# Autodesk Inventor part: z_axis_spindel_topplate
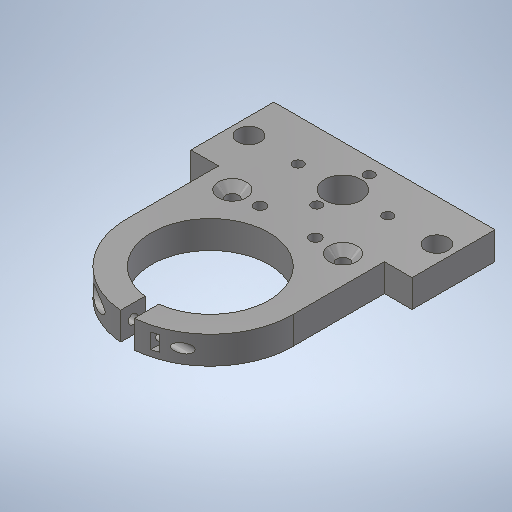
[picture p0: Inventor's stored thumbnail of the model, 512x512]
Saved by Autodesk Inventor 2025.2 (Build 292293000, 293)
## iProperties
Created: 2025-04
Part Number: z_axis_spindel_topplate
Material: 1.0037 S235JR
Document SubType Name: Modeling
Designer: BennF
Density: 7.85 g/cm^3
Appearance: Stahl
Author: BennF
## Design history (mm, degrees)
sketch "Sketch2"
  geometry: L1 (-2.5, -29.896)-(-2.5, -21.052); L2 (2.5, -29.896)-(2.5, -21.052); L3 (-30, 0)-(-30, 33); L4 (-40, 63)-(40, 63); L5 (30, 33)-(30, 0); L6 (-30, 33)-(-40, 33); L7 (-40, 33)-(-40, 63); L8 (30, 33)-(40, 33); L9 (40, 33)-(40, 63); A1 r 21.2 centre (0, 0) between (2.5, -21.052) and (-2.5, -21.052); A2 r 30 centre (0, 0) between (-30, 0) and (-2.5, -29.896); A3 r 30 centre (0, 0) between (2.5, -29.896) and (30, 0); 3 further points
  constraints: 18 end point, 7 point on circle, 4 perpendicular, 3 centre point, 3 coincident, 3 horizontal alignment, 3 vertical, 2 equal length, 2 horizontal, 1 midpoint, 1 tangent, 1 vertical alignment
  dimensions: "d0" = 5 distance between parallel lines of L2 L1; "d1" = 21.2 radius of A1; "d32" = 80 distance of L4.start L4.end; "d57" = 60 distance between parallel lines of L5 L3; "d58" = 30 distance of L4.end L8.end; "d86" = 63 distance from line of point (0, 0) L4
extrude "Extrusion1" new body sketch "Sketch2" distance "d4" = 10; taper "d5" = 0 deg
sketch "Sketch3"
  geometry: L1 (-10, 29.896)-(-10, 0) reference; L2 (-10, 0)-(0, 8.844); L3 (0, 29.896)-(0, 0) reference; L4 (0, 0)-(-10, 8.844); L5 (-10, 8.844)-(0, 8.844) reference; L6 (0, 8.844)-(0, 0) reference; L7 (0, 0)-(-10, 0) reference; L8 (-10, 0)-(-10, 8.844) reference; L9 (-10, 92.896)-(0, 92.896) reference; L10 (0, 92.896)-(0, 50.948) reference; L11 (0, 50.948)-(-10, 50.948) reference; L12 (-10, 50.948)-(-10, 92.896) reference; 2 further points
  constraints: 4 end point, 1 coincident, 1 midpoint
hole "Hole1" sketch "Sketch3" at (-5, 4.422) diameter "d6" = 3.4; stored, may be unused: countersink angle "d10" = 90 deg, drill point angle "d12" = 0 deg; dims "d7" = 3, "d8" = 6.5, "d9" = 3.4, "d11" = 3
sketch "Sketch4"
  geometry: L1 (10, 0)-(0, 0) reference; L2 (0, 0)-(0, 8.844) reference; L3 (0, 8.844)-(10, 8.844) reference; L4 (10, 8.844)-(10, 0) reference; L5 (0, 92.896)-(10, 92.896) reference; L6 (10, 92.896)-(10, 50.948) reference; L7 (10, 50.948)-(0, 50.948) reference; L8 (0, 50.948)-(0, 92.896) reference; L9 (0, 8.844)-(10, 0); L10 (0, 0)-(0, 29.896) reference; L11 (10, 8.844)-(0, 0); 2 further points
  constraints: 4 end point, 1 coincident, 1 midpoint
hole "Hole2" sketch "Sketch4" at (5, 4.422) diameter "d13" = 3.4 (= d6); stored, may be unused: countersink angle "d17" = 90 deg, drill point angle "d19" = 0 deg; dims "d14" = 6, "d15" = 4, "d16" = 2, "d18" = 8
workplane "Work Plane1"
sketch "Sketch5"
  geometry: L1 (5, 7.597)-(7.75, 6.01); L2 (7.75, 6.01)-(7.75, 2.834); L3 (7.75, 2.834)-(5, 1.246); L4 (5, 1.246)-(2.25, 2.834); L5 (2.25, 2.834)-(2.25, 6.01); L6 (2.25, 6.01)-(5, 7.597); L7 (7.75, 2.834)-(7.75, 0.848); L8 (10, 49.725)-(0, 49.725) reference; L9 (10, 10.067)-(10, 0.848) reference; L10 (10, 0.848)-(0, 0.848) reference; L11 (0, 0.848)-(0, 10.067) reference; L12 (0, 92.896)-(10, 92.896) reference; L13 (10, 92.896)-(10, 49.725) reference; L14 (0, 10.067)-(10, 10.067) reference; L15 (0, 49.725)-(0, 92.896) reference; L16 (2.25, 2.834)-(2.25, 0.848); C1 r 1.7 at (5, 4.422) reference; 3 further points
  constraints: 16 end point, 2 point on line, 1 coincident, 1 perpendicular, 1 vertical, 1 vertical alignment, 13 other
  dimensions: "d21" = 5.5 distance between parallel lines of L5 L2
extrude "Extrusion2" cut sketch "Sketch5" distance "d22" = 2.5; taper "d23" = 0 deg
sketch "Sketch6"
  geometry: L1 (50, -23.2)-(10, -23.2); L2 (70, 11.8)-(-10, 11.8) reference; 5 further points; 1 other entity
  constraints: 2 end point, 2 midpoint, 1 coincident, 1 horizontal, 1 horizontal alignment, 1 vertical alignment, 2 other
  dimensions: "d41" = 40 distance of L1.start L1.end; "d42" = 35 dimension on L1
hole "Hole3" sketch "Sketch6" at (10, -23.2), (50, -23.2) diameter "d24" = 4.5; stored, may be unused: countersink angle "d28" = 90 deg, drill point angle "d30" = 118 deg; dims "d25" = 8, "d26" = 10, "d27" = 2, "d29" = 11.8
sketch "Sketch7"
  geometry: L1 (40, -23.2)-(20, -23.2); C1 r 5 at (10, -23.2) reference; 6 further points; 1 other entity
  constraints: 2 end point, 2 horizontal alignment, 1 coincident, 1 horizontal, 1 midpoint, 1 vertical alignment, 2 other
  dimensions: "d40" = 20 distance of L1.start L1.end
hole "Hole4" sketch "Sketch7" at (40, -23.2), (20, -23.2) diameter "d33" = 4; stored, may be unused: countersink angle "d37" = 90 deg, drill point angle "d39" = 0 deg; dims "d34" = 10, "d35" = 6.5, "d36" = 3.4, "d38" = 25
sketch "Sketch8"
  geometry: L1 (-34, 48)-(34, 48); L2 (40, 63)-(-40, 63) reference; 2 further points
  constraints: 2 end point, 1 horizontal, 1 horizontal alignment, 1 midpoint, 1 vertical alignment
  dimensions: "d50" = 15 distance between parallel lines of L2 L1; "d56" = 68 distance of L1.start L1.end
hole "Hole5" sketch "Sketch8" at (-34, 48), (34, 48) diameter "d43" = 8.15; stored, may be unused: countersink angle "d47" = 90 deg, drill point angle "d49" = 118 deg; dims "d44" = 6, "d45" = 4, "d46" = 2, "d48" = 8
workplane "Work Plane2"
sketch "Sketch9"
  geometry: L1 (42.5, -10)-(70, -10) reference; L2 (46.575, -10)-(46.575, 0); L3 (61.2, 0)-(18.8, 0) reference; L4 (61.2, -10)-(18.8, -10) reference; L5 (40, 0)-(40, -10); 3 further points
  constraints: 4 end point, 2 point on line, 1 midpoint
  dimensions: "d53" = 13.15 diameter of L2 L5
revolve "Revolution1" sketch "Sketch9" stored, may be unused: angle "d55" = 90 deg
workpoint "Work Point1"
workplane "Work Plane3"
sketch "Sketch10"
  geometry: L1 (27.5, -2.05)-(5, -2.05); L2 (5, -2.05)-(5, -5); L3 (5, -5)-(27.5, -5); L4 (27.5, -5)-(27.5, -2.05); L5 (0, -6.7)-(0, -3.3) reference; L6 (27.5, -10)-(27.5, 0) reference; 2 further points
  constraints: 8 end point, 2 parallel, 1 horizontal, 1 midpoint, 1 perpendicular, 1 point on line, 1 other
  dimensions: "d59" = 5 distance between parallel lines of L5 L2; "d60" = 5.9 diameter of L1 L3
revolve "Revolution2" sketch "Sketch10" stored, may be unused: angle "d61" = 90 deg
sketch "Sketch13"
  geometry: L1 (16.2, 48)-(-16.2, 48); L2 (-40, 63)-(40, 63) reference; C1 r 6.575 at (0, 48) reference; A1 r 16.2 centre (0, 48) between (16.2, 48) and (-16.2, 48); A2 r 9.5 centre (0, 48) between (0, 38.5) and (0, 57.5); 2 further points
  constraints: 4 point on circle, 3 coincident, 2 centre point, 2 end point, 2 vertical alignment, 1 horizontal alignment, 1 midpoint
  dimensions: "d84" = 32.4 diameter of A1; "d85" = 19 diameter of A2
hole "Hole7" sketch "Sketch13" at (16.2, 48), (-16.2, 48), (0, 38.5), (0, 57.5) diameter "d76" = 3.6; stored, may be unused: countersink angle "d80" = 90 deg, drill point angle "d82" = 0 deg; dims "d77" = 6, "d78" = 7.5, "d79" = 2, "d81" = 8.8
body "Solid1"
node "Project Cut Edges1"
node "Project Cut Edges2"
node "Project Cut Edges3"
other parameters: "d20" = -5, "d51" = -15 (= -d50)
